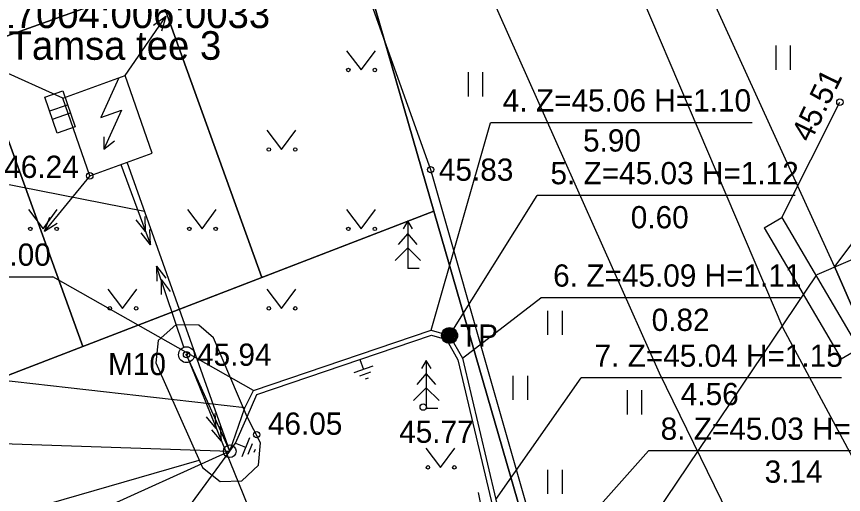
# Model space of a CAD drawing. Extents: x 642747 to 644424, y 6457048 to 6458238.
# Drawn here: x 644056.64 to 644082.64, y 6457735.52 to 6457750.55 of the extents above; entities that cross this region are included whole.
import ezdxf

# ---------------------------------------------------------------- set-up
doc = ezdxf.new("R2010")
doc.units = 0
for name, color, linetype in [('ABIJOONIS', 7, 'Continuous'), ('AED', 7, 'Continuous'), ('HALJASTUS', 7, 'Continuous'), ('HOONE', 7, 'Continuous'), ('JOONSIDE', 7, 'Continuous'), ('KOORDPUNKT', 7, 'Continuous'), ('KORGUS', 7, 'Continuous'), ('KPKAABEL', 7, 'Continuous'), ('KPOHULIIN', 7, 'Continuous'), ('MPKAABEL', 7, 'Continuous'), ('MPOHULIIN', 7, 'Continuous'), ('PIIR', 7, 'Continuous'), ('POST', 7, 'Continuous'), ('PUU', 7, 'Continuous'), ('TEE', 7, 'Continuous'), ('TRUUP', 7, 'Continuous'), ('VEEKOGU', 7, 'Continuous')]:
    doc.layers.add(name, color=color, linetype=linetype)

msp = doc.modelspace()

# ---------------------------------------------------------------- linework, layer by layer
at = {"layer": 'ABIJOONIS'}
for points in [[(644045.268, 6457745.33), (644056.066, 6457745.33), (644060.663, 6457744.428)], [(644040.302, 6457737.272), (644051.508, 6457737.272), (644063.341, 6457736.874)], [(644045.404, 6457721.568), (644052.131, 6457721.568), (644063.341, 6457736.874)], [(644039.301, 6457733.324), (644051.051, 6457733.324), (644062.377, 6457736.596)]]:
    msp.add_lwpolyline(points, dxfattribs=at)
at = {"layer": 'AED'}
msp.add_lwpolyline([(644064.587, 6457759.915), (644069.655, 6457745.733), (644073.82, 6457731.123)], dxfattribs=at)
at = {"layer": 'HALJASTUS'}
for p, q in [((644067.008, 6457749.475), (644067.471, 6457748.869)), ((644067.471, 6457748.869), (644067.917, 6457749.475)), ((644080.505, 6457749.635), (644080.505, 6457748.874)), ((644080.96, 6457749.635), (644080.96, 6457748.874)), ((644070.834, 6457748.796), (644070.834, 6457748.035)), ((644071.289, 6457748.796), (644071.289, 6457748.035)), ((644064.508, 6457746.975), (644064.971, 6457746.369)), ((644064.971, 6457746.369), (644065.417, 6457746.975)), ((644057.008, 6457744.475), (644057.471, 6457743.869)), ((644057.471, 6457743.869), (644057.917, 6457744.475)), ((644062.008, 6457744.475), (644062.471, 6457743.869)), ((644062.471, 6457743.869), (644062.917, 6457744.475)), ((644067.008, 6457744.475), (644067.471, 6457743.869)), ((644067.471, 6457743.869), (644067.917, 6457744.475)), ((644059.508, 6457741.975), (644059.971, 6457741.369)), ((644059.971, 6457741.369), (644060.417, 6457741.975)), ((644064.508, 6457741.975), (644064.971, 6457741.369)), ((644064.971, 6457741.369), (644065.417, 6457741.975)), ((644073.334, 6457741.296), (644073.334, 6457740.535)), ((644073.789, 6457741.296), (644073.789, 6457740.535)), ((644072.244, 6457739.249), (644072.244, 6457738.488)), ((644072.699, 6457739.249), (644072.699, 6457738.488)), ((644075.834, 6457738.796), (644075.834, 6457738.035)), ((644076.289, 6457738.796), (644076.289, 6457738.035)), ((644069.508, 6457736.975), (644069.971, 6457736.369)), ((644069.971, 6457736.369), (644070.417, 6457736.975)), ((644073.334, 6457736.296), (644073.334, 6457735.535)), ((644073.789, 6457736.296), (644073.789, 6457735.535))]:
    msp.add_line(p, q, dxfattribs=at)
for centre in [(644067.07, 6457748.869), (644067.899, 6457748.869), (644064.57, 6457746.369), (644065.399, 6457746.369), (644057.07, 6457743.869), (644057.899, 6457743.869), (644062.07, 6457743.869), (644062.899, 6457743.869), (644067.07, 6457743.869), (644067.899, 6457743.869), (644059.57, 6457741.369), (644060.399, 6457741.369), (644064.57, 6457741.369), (644065.399, 6457741.369), (644069.57, 6457736.369), (644070.399, 6457736.369)]:
    msp.add_circle(centre, 0.055, dxfattribs=at)
at = {"layer": 'HOONE'}
for p, q in [((644059.856, 6457748.619), (644059.288, 6457747.377)), ((644059.288, 6457747.377), (644059.935, 6457747.602)), ((644059.935, 6457747.602), (644059.38, 6457746.373)), ((644059.38, 6457746.769), (644059.38, 6457746.373)), ((644059.38, 6457746.373), (644059.711, 6457746.637))]:
    msp.add_line(p, q, dxfattribs=at)
for points in [[(644058.091, 6457747.984), (644060.05, 6457748.696)], [(644060.899, 6457746.251), (644060.05, 6457748.696)], [(644058.94, 6457745.539), (644058.091, 6457747.984)], [(644058.94, 6457745.539), (644060.899, 6457746.251)]]:
    msp.add_lwpolyline(points, dxfattribs=at)
at = {"layer": 'KOORDPUNKT'}
for p, q in [((644069.675, 6457740.685), (644071.54, 6457747.211)), ((644079.764, 6457747.211), (644071.54, 6457747.211)), ((644070.251, 6457740.516), (644073.003, 6457744.924)), ((644081.122, 6457744.924), (644073.003, 6457744.924)), ((644049.557, 6457742.36), (644057.781, 6457742.36)), ((644064.085, 6457738.786), (644057.781, 6457742.36)), ((644070.657, 6457739.804), (644073.123, 6457741.703)), ((644081.277, 6457741.703), (644073.123, 6457741.703)), ((644063.814, 6457738.243), (644049.592, 6457739.845)), ((644071.702, 6457735.361), (644074.389, 6457739.182)), ((644082.578, 6457739.182), (644074.389, 6457739.182)), ((644063.341, 6457736.874), (644051.03, 6457731.321)), ((644072.419, 6457732.308), (644076.502, 6457736.885)), ((644084.656, 6457736.885), (644076.502, 6457736.885))]:
    msp.add_line(p, q, dxfattribs=at)
for points in [[(644069.675, 6457740.685), (644069.675, 6457740.685), (644069.675, 6457740.685)], [(644070.251, 6457740.516), (644070.251, 6457740.516), (644070.251, 6457740.516)], [(644070.657, 6457739.804), (644070.657, 6457739.804), (644070.657, 6457739.804)], [(644064.085, 6457738.786), (644064.085, 6457738.786), (644064.085, 6457738.786)], [(644063.814, 6457738.243), (644063.814, 6457738.243), (644063.814, 6457738.243)], [(644063.341, 6457736.874), (644063.341, 6457736.874), (644063.341, 6457736.874)]]:
    msp.add_lwpolyline(points, dxfattribs=at)
at = {"layer": 'KORGUS'}
for centre in [(644082.522, 6457747.856), (644069.655, 6457745.733), (644058.94, 6457745.539), (644061.981, 6457739.913), (644069.423, 6457738.265), (644064.187, 6457737.395)]:
    msp.add_circle(centre, 0.1, dxfattribs=at)
at = {"layer": 'KPKAABEL'}
msp.add_lwpolyline([(644063.341, 6457736.874), (644063.814, 6457738.243), (644064.085, 6457738.786), (644069.675, 6457740.685), (644070.251, 6457740.516), (644070.657, 6457739.804), (644071.702, 6457735.361), (644072.419, 6457732.308), (644073.692, 6457725.34), (644075.548, 6457720.26), (644079.636, 6457709.071), (644081.299, 6457704.816), (644084.417, 6457695.285), (644092.153, 6457678.564), (644095.564, 6457671.153), (644098.741, 6457664.129), (644103.079, 6457652.715), (644111.131, 6457630.665)], dxfattribs=at)
at = {"layer": 'KPOHULIIN'}
for p, q in [((644059.92, 6457745.895), (644060.846, 6457743.372)), ((644060.695, 6457743.783), (644060.68, 6457744.258)), ((644060.695, 6457743.783), (644060.4, 6457744.156)), ((644060.846, 6457743.372), (644060.551, 6457743.745)), ((644060.846, 6457743.372), (644060.831, 6457743.847)), ((644061.041, 6457742.696), (644061.043, 6457742.221)), ((644061.041, 6457742.696), (644061.326, 6457742.316)), ((644061.901, 6457740.15), (644061.041, 6457742.696)), ((644061.181, 6457742.281), (644061.466, 6457741.901)), ((644061.181, 6457742.281), (644061.183, 6457741.806)), ((644062.074, 6457739.681), (644063.078, 6457737.188)), ((644062.914, 6457737.594), (644062.885, 6457738.068)), ((644062.914, 6457737.594), (644062.608, 6457737.957)), ((644063.078, 6457737.188), (644062.772, 6457737.551)), ((644063.078, 6457737.188), (644063.049, 6457737.662))]:
    msp.add_line(p, q, dxfattribs=at)
msp.add_lwpolyline([(644061.981, 6457739.913), (644094.239, 6457660.452), (644124.342, 6457586.031), (644125.691, 6457582.672)], dxfattribs=at)
at = {"layer": 'MPKAABEL'}
for points in [[(644063.341, 6457736.874), (644060.118, 6457745.967)], [(644061.645, 6457740.855), (644061.086, 6457740.358), (644061.015, 6457739.655), (644062.479, 6457736.367), (644063.038, 6457735.921), (644063.721, 6457735.949), (644064.242, 6457736.44), (644064.306, 6457737.136), (644063.885, 6457737.955), (644062.828, 6457740.444), (644062.363, 6457740.837), (644061.645, 6457740.855)], [(644063.341, 6457736.874), (644063.525, 6457737.126), (644063.885, 6457737.955), (644064.192, 6457738.663), (644067.431, 6457739.764), (644069.678, 6457740.527), (644070.15, 6457740.388), (644070.516, 6457739.748), (644071.555, 6457735.326), (644072.272, 6457732.277), (644072.571, 6457730.636)], [(644067.431, 6457739.764), (644067.542, 6457739.444)], [(644067.843, 6457739.548), (644067.242, 6457739.339)], [(644067.765, 6457739.362), (644067.418, 6457739.242)], [(644067.688, 6457739.177), (644067.594, 6457739.144)], [(644063.958, 6457737.295), (644063.722, 6457736.704)], [(644063.525, 6457737.126), (644063.84, 6457736.999)], [(644064.048, 6457737.114), (644063.911, 6457736.773)], [(644064.137, 6457736.934), (644064.1, 6457736.841)], [(644071.284, 6457734.949), (644071.161, 6457735.573)]]:
    msp.add_lwpolyline(points, dxfattribs=at)
at = {"layer": 'MPOHULIIN'}
for p, q in [((644060.05, 6457748.696), (644061.326, 6457750.549)), ((644061.326, 6457750.549), (644060.946, 6457750.263)), ((644061.326, 6457750.549), (644061.192, 6457750.093)), ((644058.091, 6457747.984), (644056.04, 6457748.908)), ((644058.94, 6457745.539), (644057.512, 6457743.8)), ((644057.512, 6457743.8), (644057.684, 6457744.243)), ((644057.512, 6457743.8), (644057.915, 6457744.053))]:
    msp.add_line(p, q, dxfattribs=at)
at = {"layer": 'PIIR'}
for points in [[(644172.44, 6457634.51), (644128.57, 6457664.58), (644105.62, 6457695.4), (644084.27, 6457738.29), (644082.35, 6457742.69), (644071.37, 6457766.77), (644068.6, 6457772.82), (644052.27, 6457804.54)], [(644056.78, 6457779.28), (644062.47, 6457766.56), (644060.34, 6457762.97), (644041.41, 6457742.89), (644054.5, 6457738.54), (644058.72, 6457740.17), (644055.31, 6457749.58), (644061, 6457751.62), (644060.21, 6457753.82), (644065.16, 6457760.36), (644069.76, 6457744.43), (644073.59, 6457731.16), (644087.56, 6457695.23), (644092.09, 6457697.08), (644102.74, 6457676.12), (644108.68, 6457668.18), (644119.21, 6457655.5), (644137.18, 6457639.57)]]:
    msp.add_lwpolyline(points, dxfattribs=at)
for points in [[(643989.66, 6457760.08), (643987.33, 6457763.78), (643977.05, 6457733.09), (644043.85, 6457709.33), (644073.59, 6457731.16), (644069.76, 6457744.43), (644054.5, 6457738.54), (644041.41, 6457742.89)], [(644065.16, 6457760.36), (644060.21, 6457753.82), (644061, 6457751.62), (644064.35, 6457742.34), (644069.76, 6457744.43)], [(644084.27, 6457738.29), (644105.62, 6457695.4), (644117.87, 6457702.68), (644141.47, 6457716.14), (644166.4, 6457723.98), (644161.44, 6457753.91), (644160.79, 6457756.77), (644152.83, 6457754.95), (644133.56, 6457751.83), (644087.35, 6457749.32), (644082.35, 6457742.69)], [(644064.35, 6457742.34), (644061, 6457751.62), (644055.31, 6457749.58), (644058.72, 6457740.17)]]:
    msp.add_lwpolyline(points, close=True, dxfattribs=at)
at = {"layer": 'POST'}
for p, q in [((644057.678, 6457747.579), (644058.242, 6457747.772)), ((644057.766, 6457747.322), (644058.331, 6457747.516))]:
    msp.add_line(p, q, dxfattribs=at)
msp.add_lwpolyline([(644057.916, 6457746.885), (644057.528, 6457748.015), (644058.093, 6457748.209), (644058.481, 6457747.079)], close=True, dxfattribs=at)
msp.add_lwpolyline([(644063.341, 6457736.874), (644061.981, 6457739.913)], dxfattribs=at)
for centre, radius in [((644070.251, 6457740.516), 0.25), ((644070.251, 6457740.516), 0.225), ((644070.251, 6457740.516), 0.2), ((644070.251, 6457740.516), 0.175), ((644070.251, 6457740.516), 0.15), ((644070.251, 6457740.516), 0.125), ((644070.251, 6457740.516), 0.1), ((644070.251, 6457740.516), 0.075), ((644070.251, 6457740.516), 0.05), ((644070.251, 6457740.516), 0.025), ((644061.981, 6457739.913), 0.25), ((644061.981, 6457739.913), 0.0234), ((644063.341, 6457736.874), 0.2)]:
    msp.add_circle(centre, radius, dxfattribs=at)
at = {"layer": 'PUU'}
for p, q in [((644068.937, 6457744.124), (644068.787, 6457743.874)), ((644069.087, 6457743.874), (644068.937, 6457744.124)), ((644068.937, 6457744.124), (644068.937, 6457742.624)), ((644068.937, 6457743.724), (644068.637, 6457743.374)), ((644069.237, 6457743.374), (644068.937, 6457743.724)), ((644068.937, 6457743.274), (644068.537, 6457742.874)), ((644069.337, 6457742.874), (644068.937, 6457743.274)), ((644069.297, 6457742.624), (644068.937, 6457742.624)), ((644069.52, 6457739.725), (644069.37, 6457739.475)), ((644069.67, 6457739.475), (644069.52, 6457739.725)), ((644069.52, 6457739.725), (644069.52, 6457738.225)), ((644069.52, 6457739.325), (644069.22, 6457738.975)), ((644069.82, 6457738.975), (644069.52, 6457739.325)), ((644069.52, 6457738.875), (644069.12, 6457738.475)), ((644069.92, 6457738.475), (644069.52, 6457738.875)), ((644069.88, 6457738.225), (644069.52, 6457738.225))]:
    msp.add_line(p, q, dxfattribs=at)
at = {"layer": 'TEE'}
for points in [[(644061.722, 6457771.823), (644064.397, 6457766.262), (644069.452, 6457755.916), (644076.842, 6457739.337), (644084.183, 6457724.283), (644091.562, 6457708.571), (644100.441, 6457690.483), (644108.831, 6457675.729), (644120.122, 6457661.417), (644128.409, 6457653.611)], [(644104.514, 6457693.442), (644104.136, 6457693.495), (644095.975, 6457711.092), (644088.251, 6457726.755), (644080.737, 6457740.751), (644073.333, 6457758.14), (644069.994, 6457765.435), (644069.979, 6457766.674)]]:
    msp.add_lwpolyline(points, dxfattribs=at)
at = {"layer": 'TRUUP'}
msp.add_line((644076.161, 6457734.051), (644081.798, 6457742.429), dxfattribs=at)
for points in [[(644080.146, 6457743.9), (644080.701, 6457744.227), (644083.122, 6457740.111)], [(644080.146, 6457743.9), (644082.567, 6457739.784), (644083.122, 6457740.111)], [(644090.359, 6457743.948), (644085.334, 6457743.948), (644081.798, 6457742.429)]]:
    msp.add_lwpolyline(points, dxfattribs=at)
at = {"layer": 'VEEKOGU'}
msp.add_lwpolyline([(644080.701, 6457744.227), (644082.522, 6457747.856)], dxfattribs=at)

# ---------------------------------------------------------------- texts
at = {"layer": 'JOONSIDE'}
for s, p in [('5.90', (644074.447, 6457746.302)), ('0.60', (644075.948, 6457743.888)), ('0.82', (644076.604, 6457740.66)), ('4.56', (644077.521, 6457738.325)), ('3.14', (644080.157, 6457735.885))]:
    msp.add_text(s, height=0.7, dxfattribs=at).set_placement(p)
at = {"layer": 'KOORDPUNKT'}
for s, p in [('4. Z=45.06 H=1.10', (644071.925, 6457747.561)), ('5. Z=45.03 H=1.12', (644073.423, 6457745.274)), ('3. Z=45.06 H=1.00', (644049.907, 6457742.71)), ('6. Z=45.09 H=1.11', (644073.508, 6457742.053)), ('7. Z=45.04 H=1.15', (644074.809, 6457739.532)), ('8. Z=45.03 H=1.16', (644076.887, 6457737.235))]:
    msp.add_text(s, height=0.7, dxfattribs=at).set_placement(p)
at = {"layer": 'KORGUS'}
msp.add_text(' 45.51', height=0.7, rotation=64.0387, dxfattribs=at).set_placement((644081.481, 6457746.325))
for s, p in [('46.24', (644056.25, 6457745.473)), (' 45.83', (644069.655, 6457745.383)), ('45.94', (644062.311, 6457739.563)), ('46.05', (644064.537, 6457737.395)), ('45.77', (644068.666, 6457737.14))]:
    msp.add_text(s, height=0.7, dxfattribs=at).set_placement(p)
at = {"layer": 'PIIR'}
for s, p in [('17004:006:0033', (644055.91, 6457750.186)), ('Tamsa tee 3', (644056.383, 6457749.189))]:
    msp.add_text(s, height=0.9, dxfattribs=at).set_placement(p)
at = {"layer": 'POST'}
for s, p in [('TP', (644070.577, 6457740.163)), ('M10', (644059.513, 6457739.269))]:
    msp.add_text(s, height=0.7, dxfattribs=at).set_placement(p)

doc.saveas('drawing.dxf')
